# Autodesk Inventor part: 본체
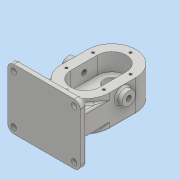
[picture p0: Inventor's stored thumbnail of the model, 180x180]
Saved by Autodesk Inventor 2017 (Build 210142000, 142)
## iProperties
Part Number: 본체
Material: 일반
Document SubType Name: Modeling
Designer: 7-1
Density: 1 g/cm^3
Appearance: 기본값
Author: 7-1
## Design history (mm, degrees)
sketch "스케치1"
  geometry: L1 (0, 0)-(0, 44); L2 (-40, 0)-(-40, 44); L3 (40, 44)-(40, 0); A1 r 40 centre (0, 0) between (-40, 0) and (40, 0); A2 r 40 centre (0, 44) between (40, 44) and (-40, 44); 1 further point
  constraints: 8 end point, 4 point on circle, 4 tangent, 2 centre point, 1 midpoint, 1 parallel, 1 vertical
  dimensions: "d0" = 80 distance between parallel lines of L3 L2; "d1" = 124 dimension on A1 A2
extrude "돌출1" new body sketch "스케치1" distance "d2" = 53; taper "d3" = 0 deg
sketch "스케치2"
  geometry: L1 (0, 0)-(0, 44); L2 (-24, 0)-(-24, 44); L3 (24, 44)-(24, 0); A1 r 24 centre (0, 0) between (-24, 0) and (24, 0); A2 r 24 centre (0, 44) between (24, 44) and (-24, 44); 1 further point
  constraints: 8 end point, 4 point on circle, 4 tangent, 2 centre point, 1 midpoint, 1 parallel, 1 vertical
  dimensions: "d4" = 24 radius of A2; "d5" = 92 dimension on A1 A2
extrude "돌출2" cut sketch "스케치2" distance "d6" = 29; taper "d7" = 0 deg
sketch "스케치3"
  geometry: C1 r 12.5 at (0, 0); C2 r 12.5 at (0, 44); 1 further point
  constraints: 2 centre point, 1 coincident, 1 vertical alignment
  dimensions: "d8" = 25 diameter of C1; "d9" = 25 diameter of C2; "d10" = 44 distance of point (0, 0) C2.centre
extrude "돌출3" cut sketch "스케치3" distance "d11" = 15; taper "d12" = 0 deg
sketch "스케치4"
  geometry: C1 r 19 at (0, 44); 1 further point
  constraints: 1 centre point, 1 vertical alignment
  dimensions: "d13" = 38 diameter of C1; "d14" = 44 distance of point (0, 0) C1.centre
extrude "돌출4" join sketch "스케치4" distance "d15" = 17; taper "d16" = 0 deg
hole "구멍1" diameter "d19" = 17; stored, may be unused: countersink angle "d23" = 90 deg, drill point angle "d25" = 118 deg; dims "d17" = 10, "d18" = 10, "d20" = 6, "d21" = 28, "d22" = 7.3, "d24" = 8
sketch "스케치5"
  geometry: L1 (-40, 44)-(-40, 0) reference; L2 (40, 0)-(40, 44) reference; L3 (31, 44)-(31, 0); L4 (-31, 0)-(-31, 44); A1 r 40 centre (0, 44) between (40, 44) and (-40, 44) reference; A2 r 40 centre (0, 0) between (-40, 0) and (40, 0) reference; A3 r 31 centre (0, 44) between (31, 44) and (-31, 44); A4 r 31 centre (0, 0) between (-31, 0) and (31, 0); 7 further points
  constraints: 6 point on circle, 4 coincident, 4 end point, 2 centre point, 3 other
  dimensions: "d26" = 9 radial gap between concentric circles of A1 A3
hole "구멍2" sketch "스케치5" at (0, 75), (-31, 44), (-31, 0), (31, 0), (31, 44), (0, -31) diameter "d27" = 4.134; stored, may be unused: countersink angle "d31" = 90 deg, drill point angle "d33" = 118 deg; dims "d28" = 10, "d29" = 28, "d30" = 7.3, "d32" = 12
chamfer "모따기1" distance "d34" = 0.7; stored, may be unused: second distance "d35" = 2, angle "d36" = 30 deg
fillet "모깎기1" dims "d37" = 0.5
chamfer "모따기2" distance "d38" = 1; stored, may be unused: second distance "d39" = 2, angle "d40" = 30 deg
node "작업 평면1"
node "작업 평면2"
node "작업 평면3"
sketch "스케치6"
  geometry: L1 (-19, -17)-(19, -17) reference; L2 (60, 83)-(-60, 83); L3 (-60, 83)-(-60, -17); L4 (-60, -17)-(60, -17); L5 (60, -17)-(60, 83); 2 further points
  constraints: 8 end point, 2 midpoint, 2 parallel, 1 horizontal, 1 perpendicular
  dimensions: "d44" = 120 distance of L4.end L3.end; "d45" = 100 distance of L3.end L2.end
extrude "돌출5" join sketch "스케치6" distance "d46" = 10; taper "d47" = 0 deg
sketch "스케치7"
  geometry: L1 (19, 17)-(-19, 17) reference; L2 (-40, -45)-(40, -45); L3 (40, -45)-(40, -8); L4 (40, -8)-(-40, -8); L5 (-40, -8)-(-40, -45); 2 further points
  constraints: 8 end point, 2 parallel, 1 horizontal, 1 midpoint, 1 perpendicular, 1 vertical alignment
  dimensions: "d48" = 80 distance of L4.end L3.end; "d49" = 37 distance of L3.end L2.end; "d50" = 25 distance between parallel lines of L4 L1
extrude "돌출6" join sketch "스케치7" stored distance "d51" = 10; taper "d52" = 0 deg
sketch "스케치8"
  geometry: L1 (0, 84)-(-53, 84) reference; L2 (-53, 0)-(-53, 44) reference; L3 (-83, -68)-(17, -68) reference; C1 r 11 at (-39, 22); 1 further point
  constraints: 1 centre point
  dimensions: "d53" = 22 diameter of C1; "d54" = 14 distance from line of C1.centre L2; "d55" = 90 distance from line of L3 C1.centre
extrude "돌출7" join sketch "스케치8" distance "d56" = 10; taper "d57" = 0 deg
hole "구멍3" diameter "d60" = 8.376; stored, may be unused: countersink angle "d64" = 90 deg, drill point angle "d66" = 118 deg; dims "d61" = 20, "d62" = 28, "d63" = 7.3, "d65" = 35, "d83" = 10, "d84" = 10
fillet "모깎기2" dims "d67" = 10
sketch "스케치9"
  geometry: L1 (50, 17)-(-50, 17) reference; L2 (60, -73)-(60, 7) reference; L3 (-50, -83)-(50, -83) reference; L4 (-60, 7)-(-60, -73) reference; A1 r 10 centre (-50, 7) between (-50, 17) and (-60, 7) reference; A2 r 10 centre (50, 7) between (60, 7) and (50, 17) reference; A3 r 10 centre (50, -73) between (50, -83) and (60, -73) reference; A4 r 10 centre (-50, -73) between (-60, -73) and (-50, -83) reference; 5 further points
  constraints: 4 coincident
hole "구멍4" sketch "스케치9" at (-50, -73), (-50, 7), (50, 7), (50, -73) diameter "d68" = 9; stored, may be unused: countersink angle "d72" = 90 deg, drill point angle "d74" = 118 deg; dims "d69" = 20, "d70" = 28, "d71" = 7.3, "d73" = 35
sketch "스케치10"
  geometry: L1 (-50, -83)-(50, -83) reference; L2 (-60, 7)-(-60, -73) reference; 2 further points
  constraints: 1 other
  dimensions: "d75" = 12 distance from line of L1 point (0, -71); "d76" = 60 distance from line of point (0, -71) L2
feature "엠보싱1" sketch "스케치10" dims "d0" = 80, "d1" = 124, "d9" = 25, "d10" = 44, "d77" = 0.5, "d78" = 0
fillet "모깎기3" dims "d79" = 3
fillet "모깎기4" dims "d80" = 3
fillet "모깎기5" dims "d81" = 3
fillet "모깎기6" dims "d82" = 3
node "솔리드1"
mirror "미러1"
node "투영된 루프1"
other parameters: "d41" = 84, "d42" = 125, "d43" = -152
